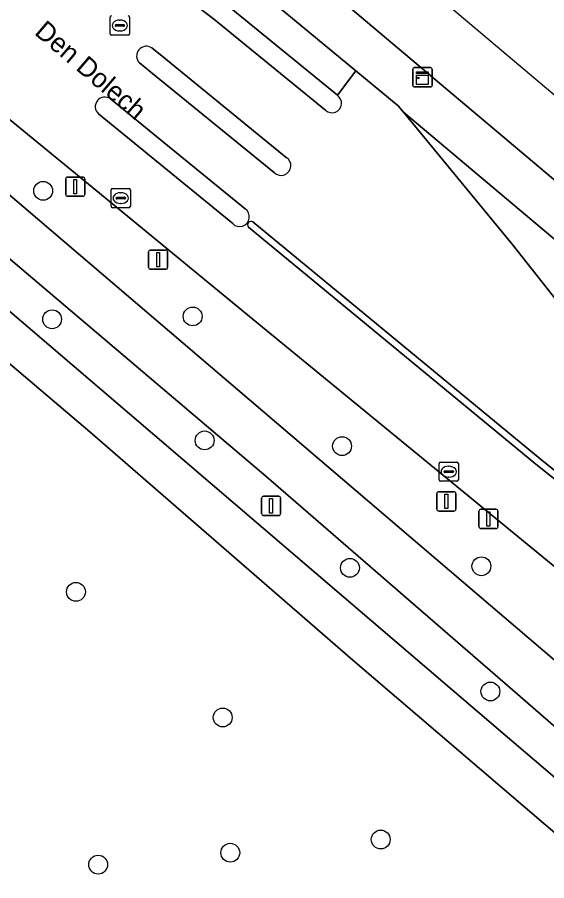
# Model space of a CAD drawing. Extents: x 161477 to 163040, y 383680 to 384871.
# Drawn here: x 161706.02 to 161733.53, y 384492.44 to 384537.26 of the extents above; entities that cross this region are included whole.
import ezdxf

# ---------------------------------------------------------------- set-up
doc = ezdxf.new("R2010")
doc.units = 0
for name, color, linetype in [('IMGEO_Berm_groen', 7, 'Continuous'), ('IMGEO_Boom', 7, 'Continuous'), ('IMGEO_Fietspad_gesloten', 7, 'Continuous'), ('IMGEO_Groenvoorziening', 7, 'Continuous'), ('IMGEO_Hek', 7, 'Continuous'), ('IMGEO_Kast', 7, 'Continuous'), ('IMGEO_Kolk', 7, 'Continuous'), ('IMGEO_Lichtmast', 7, 'Continuous'), ('IMGEO_Openbare_ruimte_label', 7, 'Continuous'), ('IMGEO_Rijbaan_lokaal_gesloten', 7, 'Continuous'), ('IMGEO_Rioolput', 7, 'Continuous'), ('IMGEO_Verkeersbordpaal', 7, 'Continuous'), ('IMGEO_Verkeerseiland_open', 7, 'Continuous'), ('IMGEO_Voetpad_open', 7, 'Continuous')]:
    doc.layers.add(name, color=color, linetype=linetype)

msp = doc.modelspace()

# ---------------------------------------------------------------- linework, layer by layer
at = {"layer": 'IMGEO_Berm_groen'}
for points in [[(161678.56, 384547.407), (161677.753, 384545.804), (161681.058, 384542.99), (161731.371, 384500), (161746.134, 384487.423), (161749.434, 384491.319), (161747.506, 384491.552)], [(161742.471, 384493.27), (161738.494, 384496.491), (161732.151, 384501.995), (161718.936, 384513.436), (161679.396, 384546.949)], [(161718.281, 384521.57), (161710.962, 384527.577), (161699.909, 384536.614), (161698.057, 384534.466), (161738.175, 384500.28), (161743.793, 384495.549), (161744.856, 384494.9), (161745.876, 384494.553)], [(161747.505, 384494.173), (161751.746, 384494.05), (161748.886, 384496.485), (161744.99, 384499.712), (161736.359, 384506.763), (161728.362, 384513.296), (161718.281, 384521.57)]]:
    msp.add_lwpolyline(points, dxfattribs=at)
msp.add_lwpolyline([(161726.09, 384532.33), (161731.734, 384525.482), (161735.698, 384520.457), (161737.128, 384518.817), (161738.213, 384517.796), (161738.289, 384517.727), (161738.506, 384517.532), (161739.38, 384516.745), (161750.717, 384507.564), (161752.219, 384506.212), (161757.111, 384501.401), (161757.185, 384501.335), (161758.111, 384502.394), (161757.471, 384504.592), (161756.765, 384506.541)], close=True, dxfattribs=at)
at = {"layer": 'IMGEO_Boom'}
for centre in [(161707.364, 384528.249), (161715.13, 384521.73), (161707.826, 384521.581), (161715.753, 384515.295), (161722.89, 384514.999), (161723.301, 384508.681), (161730.13, 384508.76), (161709.066, 384507.434), (161730.595, 384502.262), (161716.69, 384500.914), (161724.9, 384494.578), (161717.084, 384493.895), (161710.221, 384493.274)]:
    msp.add_circle(centre, 0.489, dxfattribs=at)
at = {"layer": 'IMGEO_Fietspad_gesloten'}
for points in [[(161679.396, 384546.949), (161718.936, 384513.436), (161732.151, 384501.995), (161738.494, 384496.491), (161742.471, 384493.27)], [(161716.468, 384538.263), (161722.646, 384533.207), (161723.613, 384534.474), (161717.624, 384539.425)], [(161745.876, 384494.553), (161744.856, 384494.9), (161743.793, 384495.549), (161738.175, 384500.28), (161698.057, 384534.466)]]:
    msp.add_lwpolyline(points, dxfattribs=at)
at = {"layer": 'IMGEO_Groenvoorziening'}
for points in [[(161725.311, 384630.208), (161692.773, 384563.441), (161758.806, 384507.866), (161760.886, 384500.893), (161760.961, 384500.987), (161761.131, 384500.854)], [(161655.123, 384380.786), (161705.198, 384439.501), (161703.363, 384440.983), (161707.91, 384446.382), (161709.855, 384444.859), (161729.976, 384468.339), (161744.705, 384485.735), (161723.453, 384503.883), (161709.781, 384515.739), (161680.014, 384540.993), (161676.741, 384543.785), (161660.175, 384511.161), (161637.594, 384466.689), (161619.35, 384430.848), (161600.945, 384394.608), (161593.687, 384380.342), (161587.084, 384366.964)]]:
    msp.add_lwpolyline(points, dxfattribs=at)
at = {"layer": 'IMGEO_Hek'}
msp.add_lwpolyline([(161694.364, 384566.706), (161703.664, 384558.776), (161724.439, 384541.249), (161745.033, 384523.877), (161742.926, 384521.23)], dxfattribs=at)
at = {"layer": 'IMGEO_Kast'}
for p, q in [((161726.569, 384533.718), (161726.569, 384534.559)), ((161726.569, 384534.559), (161726.569, 384533.718)), ((161726.644, 384534.643), (161727.485, 384534.643)), ((161727.485, 384534.643), (161726.644, 384534.643)), ((161727.569, 384534.568), (161727.569, 384533.727)), ((161727.569, 384533.727), (161727.569, 384534.568)), ((161727.494, 384533.643), (161726.653, 384533.643)), ((161726.653, 384533.643), (161727.494, 384533.643))]:
    msp.add_line(p, q, dxfattribs=at)
for points in [[(161726.764, 384534.433), (161727.364, 384534.433), (161727.364, 384534.348), (161726.764, 384534.348), (161726.764, 384534.433)], [(161726.764, 384534.258), (161727.364, 384534.258), (161727.364, 384533.769), (161726.764, 384533.769), (161726.764, 384534.258)]]:
    msp.add_lwpolyline(points, dxfattribs=at)
msp.add_circle((161726.848, 384534.107), 0.0377, dxfattribs=at)
for centre, start, end in [((161726.647, 384534.565), 92.4484, 184.2845), ((161726.647, 384534.565), 92.4484, 184.2845), ((161727.491, 384534.565), 2.4484, 94.2845), ((161727.491, 384534.565), 2.4484, 94.2845), ((161726.647, 384533.721), 182.4484, 274.2845), ((161726.647, 384533.721), 182.4484, 274.2845), ((161727.491, 384533.721), 272.4484, 4.2845), ((161727.491, 384533.721), 272.4484, 4.2845)]:
    msp.add_arc(centre, 0.0779, start, end, dxfattribs=at)
at = {"layer": 'IMGEO_Kolk'}
for p, q in [((161710.893, 384527.446), (161710.893, 384528.298)), ((161710.968, 384528.372), (161711.82, 384528.372)), ((161711.381, 384528.152), (161711.406, 384528.152)), ((161711.894, 384528.298), (161711.894, 384527.446)), ((161711.152, 384527.866), (161711.152, 384527.878)), ((161711.59, 384527.829), (161711.192, 384527.829)), ((161711.195, 384527.915), (161711.593, 384527.915)), ((161711.404, 384527.592), (161711.379, 384527.592)), ((161711.636, 384527.878), (161711.636, 384527.866)), ((161711.82, 384527.372), (161710.968, 384527.372)), ((161727.932, 384513.247), (161727.932, 384514.099)), ((161728.007, 384514.173), (161728.859, 384514.173)), ((161728.933, 384514.099), (161728.933, 384513.247)), ((161728.191, 384513.667), (161728.191, 384513.679)), ((161728.629, 384513.63), (161728.231, 384513.63)), ((161728.234, 384513.716), (161728.632, 384513.716)), ((161728.42, 384513.953), (161728.445, 384513.953)), ((161728.675, 384513.679), (161728.675, 384513.667)), ((161728.443, 384513.393), (161728.418, 384513.393)), ((161728.859, 384513.173), (161728.007, 384513.173))]:
    msp.add_line(p, q, dxfattribs=at)
for points in [[(161710.893, 384527.446), (161710.893, 384528.298)], [(161710.968, 384528.372), (161711.82, 384528.372)], [(161711.894, 384528.298), (161711.894, 384527.446)], [(161711.82, 384527.372), (161710.968, 384527.372)], [(161727.932, 384513.247), (161727.932, 384514.099)], [(161728.007, 384514.173), (161728.859, 384514.173)], [(161728.933, 384514.099), (161728.933, 384513.247)], [(161728.859, 384513.173), (161728.007, 384513.173)]]:
    msp.add_lwpolyline(points, dxfattribs=at)
for centre, radius, start, end in [((161710.97, 384528.296), 0.0765, 91.552, 178.448), ((161710.97, 384528.296), 0.0765, 91.552, 178.448), ((161711.818, 384528.296), 0.0765, 1.552, 88.448), ((161711.818, 384528.296), 0.0765, 1.552, 88.448), ((161711.192, 384527.875), 0.0403, 85.8775, 175.7526), ((161711.189, 384527.865), 0.0366, 178.938, 274.7102), ((161711.593, 384527.872), 0.043, 264.8664, 352.4533), ((161711.597, 384527.877), 0.0386, 1.7309, 96.639), ((161710.97, 384527.448), 0.0765, 181.552, 268.448), ((161710.97, 384527.448), 0.0765, 181.552, 268.448), ((161711.818, 384527.448), 0.0765, 271.552, 358.448), ((161711.818, 384527.448), 0.0765, 271.552, 358.448), ((161728.009, 384514.097), 0.0765, 91.552, 178.448), ((161728.009, 384514.097), 0.0765, 91.552, 178.448), ((161728.857, 384514.097), 0.0765, 1.552, 88.448), ((161728.857, 384514.097), 0.0765, 1.552, 88.448), ((161728.231, 384513.676), 0.0403, 85.8775, 175.7526), ((161728.228, 384513.666), 0.0366, 178.938, 274.7102), ((161728.632, 384513.673), 0.043, 264.8664, 352.4533), ((161728.636, 384513.678), 0.0386, 1.7309, 96.639), ((161728.009, 384513.249), 0.0765, 181.552, 268.448), ((161728.009, 384513.249), 0.0765, 181.552, 268.448), ((161728.857, 384513.249), 0.0765, 271.552, 358.448), ((161728.857, 384513.249), 0.0765, 271.552, 358.448)]:
    msp.add_arc(centre, radius, start, end, dxfattribs=at)
for centre, major_axis, ratio, start_param, end_param in [((161711.38, 384527.872), (-0.387, 0.002), 0.722429, 4.712389, 7.853982), ((161711.405, 384527.872), (-0.39, 0.002), 0.717154, 1.570796, 4.712389), ((161728.419, 384513.673), (-0.387, 0.002), 0.722429, 4.712389, 7.853982), ((161728.444, 384513.673), (-0.39, 0.002), 0.717154, 1.570796, 4.712389)]:
    msp.add_ellipse(centre, major_axis=major_axis, ratio=ratio, start_param=start_param, end_param=end_param, dxfattribs=at)
at = {"layer": 'IMGEO_Lichtmast'}
for p, q in [((161708.632, 384528.964), (161709.422, 384528.964)), ((161709.422, 384528.964), (161708.632, 384528.964)), ((161708.532, 384528.064), (161708.532, 384528.864)), ((161708.532, 384528.864), (161708.532, 384528.064)), ((161709.522, 384528.864), (161709.522, 384528.064)), ((161709.522, 384528.064), (161709.522, 384528.864)), ((161709.422, 384527.964), (161708.632, 384527.964)), ((161708.632, 384527.964), (161709.422, 384527.964)), ((161712.84, 384524.276), (161712.84, 384525.076)), ((161712.84, 384525.076), (161712.84, 384524.276)), ((161712.94, 384525.176), (161713.73, 384525.176)), ((161713.73, 384525.176), (161712.94, 384525.176)), ((161713.83, 384525.076), (161713.83, 384524.276)), ((161713.83, 384524.276), (161713.83, 384525.076)), ((161713.73, 384524.176), (161712.94, 384524.176)), ((161712.94, 384524.176), (161713.73, 384524.176)), ((161718.708, 384511.498), (161718.708, 384512.298)), ((161718.708, 384512.298), (161718.708, 384511.498)), ((161718.808, 384512.398), (161719.598, 384512.398)), ((161719.598, 384512.398), (161718.808, 384512.398)), ((161719.698, 384512.298), (161719.698, 384511.498)), ((161719.698, 384511.498), (161719.698, 384512.298)), ((161727.815, 384511.73), (161727.815, 384512.53)), ((161727.815, 384512.53), (161727.815, 384511.73)), ((161727.915, 384512.63), (161728.705, 384512.63)), ((161728.705, 384512.63), (161727.915, 384512.63)), ((161728.805, 384512.53), (161728.805, 384511.73)), ((161728.805, 384511.73), (161728.805, 384512.53)), ((161719.598, 384511.398), (161718.808, 384511.398)), ((161718.808, 384511.398), (161719.598, 384511.398)), ((161728.705, 384511.63), (161727.915, 384511.63)), ((161727.915, 384511.63), (161728.705, 384511.63))]:
    msp.add_line(p, q, dxfattribs=at)
for points in [[(161708.952, 384528.839), (161709.102, 384528.839), (161709.102, 384528.089), (161708.952, 384528.089), (161708.952, 384528.839)], [(161713.26, 384525.051), (161713.41, 384525.051), (161713.41, 384524.301), (161713.26, 384524.301), (161713.26, 384525.051)], [(161728.235, 384512.505), (161728.385, 384512.505), (161728.385, 384511.755), (161728.235, 384511.755), (161728.235, 384512.505)], [(161719.128, 384512.273), (161719.278, 384512.273), (161719.278, 384511.523), (161719.128, 384511.523), (161719.128, 384512.273)]]:
    msp.add_lwpolyline(points, dxfattribs=at)
for centre, start, end in [((161708.632, 384528.864), 90, 180), ((161708.632, 384528.864), 90, 180), ((161709.422, 384528.864), 0, 90), ((161709.422, 384528.864), 360, 90), ((161708.632, 384528.064), 180, 270), ((161708.632, 384528.064), 180, 270), ((161709.422, 384528.064), 270, 0), ((161709.422, 384528.064), 270, 0), ((161712.94, 384525.076), 90, 180), ((161712.94, 384525.076), 90, 180), ((161713.73, 384525.076), 0, 90), ((161713.73, 384525.076), 360, 90), ((161712.94, 384524.276), 180, 270), ((161712.94, 384524.276), 180, 270), ((161713.73, 384524.276), 270, 0), ((161713.73, 384524.276), 270, 0), ((161718.808, 384512.298), 90, 180), ((161718.808, 384512.298), 90, 180), ((161719.598, 384512.298), 0, 90), ((161719.598, 384512.298), 360, 90), ((161727.915, 384512.53), 90, 180), ((161727.915, 384512.53), 90, 180), ((161728.705, 384512.53), 0, 90), ((161728.705, 384512.53), 360, 90), ((161718.808, 384511.498), 180, 270), ((161718.808, 384511.498), 180, 270), ((161719.598, 384511.498), 270, 0), ((161719.598, 384511.498), 270, 0), ((161727.915, 384511.73), 180, 270), ((161727.915, 384511.73), 180, 270), ((161728.705, 384511.73), 270, 0), ((161728.705, 384511.73), 270, 0)]:
    msp.add_arc(centre, 0.1, start, end, dxfattribs=at)
at = {"layer": 'IMGEO_Rijbaan_lokaal_gesloten'}
for points in [[(161722.044, 384532.421), (161716.216, 384537.169), (161711.444, 384540.818)], [(161699.909, 384536.614), (161710.962, 384527.577), (161718.281, 384521.57), (161728.362, 384513.296), (161736.359, 384506.763)], [(161713.011, 384535.666), (161713.624, 384535.169), (161719.996, 384529.987)], [(161712.954, 384534.417), (161712.364, 384534.895)], [(161719.376, 384529.19), (161712.954, 384534.417)], [(161726.09, 384532.33), (161725.811, 384532.656), (161723.613, 384534.474), (161722.646, 384533.207)], [(161710.855, 384533.023), (161711.435, 384532.549), (161711.532, 384532.47), (161713.639, 384530.75)], [(161717.208, 384526.545), (161710.231, 384532.253)], [(161735.698, 384520.457), (161731.734, 384525.482), (161726.09, 384532.33)], [(161713.639, 384530.75), (161717.85, 384527.315)], [(161718.26, 384526.644), (161733.182, 384514.341), (161736.308, 384511.837), (161739.469, 384509.368), (161756.636, 384495.993)], [(161756.636, 384495.993), (161756.418, 384495.733), (161739.259, 384509.1), (161736.098, 384511.571), (161732.954, 384514.063), (161718.034, 384526.362)]]:
    msp.add_lwpolyline(points, dxfattribs=at)
for centre, radius, start, end in [((161712.723, 384535.251), 0.505, 55.2503, 224.7449), ((161710.565, 384532.62), 0.496, 54.2569, 227.7012), ((161722.366, 384532.798), 0.496, 229.4221, 55.6807), ((161719.726, 384529.557), 0.507, 226.3478, 57.8922), ((161717.57, 384526.896), 0.504, 224.091, 56.2686), ((161718.17, 384526.485), 0.183, 60.4706, 222.1107)]:
    msp.add_arc(centre, radius, start, end, dxfattribs=at)
at = {"layer": 'IMGEO_Rioolput'}
for p, q in [((161710.846, 384536.406), (161710.846, 384537.258)), ((161711.334, 384537.112), (161711.359, 384537.112)), ((161711.847, 384537.258), (161711.847, 384536.406)), ((161711.105, 384536.826), (161711.105, 384536.838)), ((161711.543, 384536.789), (161711.145, 384536.789)), ((161711.148, 384536.875), (161711.546, 384536.875)), ((161711.357, 384536.552), (161711.332, 384536.552)), ((161711.589, 384536.838), (161711.589, 384536.826)), ((161711.773, 384536.332), (161710.921, 384536.332))]:
    msp.add_line(p, q, dxfattribs=at)
for points in [[(161710.846, 384536.406), (161710.846, 384537.258)], [(161711.847, 384537.258), (161711.847, 384536.406)], [(161711.773, 384536.332), (161710.921, 384536.332)]]:
    msp.add_lwpolyline(points, dxfattribs=at)
for centre, radius, start, end in [((161710.923, 384537.256), 0.0765, 91.552, 178.448), ((161710.923, 384537.256), 0.0765, 91.552, 178.448), ((161711.771, 384537.256), 0.0765, 1.552, 88.448), ((161711.771, 384537.256), 0.0765, 1.552, 88.448), ((161711.145, 384536.835), 0.0403, 85.8775, 175.7526), ((161711.142, 384536.825), 0.0366, 178.938, 274.7102), ((161711.546, 384536.832), 0.043, 264.8664, 352.4533), ((161711.55, 384536.837), 0.0386, 1.7309, 96.639), ((161710.923, 384536.408), 0.0765, 181.552, 268.448), ((161710.923, 384536.408), 0.0765, 181.552, 268.448), ((161711.771, 384536.408), 0.0765, 271.552, 358.448), ((161711.771, 384536.408), 0.0765, 271.552, 358.448)]:
    msp.add_arc(centre, radius, start, end, dxfattribs=at)
for centre, major_axis, ratio, start_param, end_param in [((161711.333, 384536.832), (-0.387, 0.002), 0.722429, 4.712389, 7.853982), ((161711.358, 384536.832), (-0.39, 0.002), 0.717154, 1.570796, 4.712389)]:
    msp.add_ellipse(centre, major_axis=major_axis, ratio=ratio, start_param=start_param, end_param=end_param, dxfattribs=at)
at = {"layer": 'IMGEO_Verkeersbordpaal'}
for p, q in [((161729.998, 384510.821), (161729.998, 384511.621)), ((161729.998, 384511.621), (161729.998, 384510.821)), ((161730.098, 384511.721), (161730.888, 384511.721)), ((161730.888, 384511.721), (161730.098, 384511.721)), ((161730.988, 384511.621), (161730.988, 384510.821)), ((161730.988, 384510.821), (161730.988, 384511.621)), ((161730.888, 384510.721), (161730.098, 384510.721)), ((161730.098, 384510.721), (161730.888, 384510.721))]:
    msp.add_line(p, q, dxfattribs=at)
msp.add_lwpolyline([(161730.418, 384511.596), (161730.568, 384511.596), (161730.568, 384510.846), (161730.418, 384510.846), (161730.418, 384511.596)], dxfattribs=at)
for centre, start, end in [((161730.098, 384511.621), 90, 180), ((161730.098, 384511.621), 90, 180), ((161730.888, 384511.621), 0, 90), ((161730.888, 384511.621), 360, 90), ((161730.098, 384510.821), 180, 270), ((161730.098, 384510.821), 180, 270), ((161730.888, 384510.821), 270, 0), ((161730.888, 384510.821), 270, 0)]:
    msp.add_arc(centre, 0.1, start, end, dxfattribs=at)
at = {"layer": 'IMGEO_Verkeerseiland_open'}
for points in [[(161703.129, 384547.68), (161699.289, 384550.909), (161698.747, 384550.205), (161704.786, 384545.311), (161711.444, 384540.818), (161716.216, 384537.169), (161722.044, 384532.421)], [(161722.646, 384533.207), (161716.468, 384538.263)], [(161713.624, 384535.169), (161713.011, 384535.666)], [(161719.996, 384529.987), (161713.624, 384535.169)], [(161712.364, 384534.895), (161712.954, 384534.417), (161719.376, 384529.19)], [(161713.639, 384530.75), (161711.532, 384532.47), (161711.435, 384532.549), (161710.855, 384533.023)], [(161710.231, 384532.253), (161717.208, 384526.545)], [(161717.85, 384527.315), (161713.639, 384530.75)], [(161718.034, 384526.362), (161732.954, 384514.063), (161736.098, 384511.571), (161739.259, 384509.1), (161756.418, 384495.733), (161756.636, 384495.993), (161739.469, 384509.368), (161736.308, 384511.837), (161733.182, 384514.341), (161718.26, 384526.644)]]:
    msp.add_lwpolyline(points, dxfattribs=at)
for centre, radius, start, end in [((161712.723, 384535.251), 0.505, 55.2503, 224.7449), ((161710.565, 384532.62), 0.496, 54.2569, 227.7012), ((161722.366, 384532.798), 0.496, 229.4221, 55.6807), ((161719.726, 384529.557), 0.507, 226.3478, 57.8922), ((161717.57, 384526.896), 0.504, 224.091, 56.2686), ((161718.17, 384526.485), 0.183, 60.4706, 222.1107)]:
    msp.add_arc(centre, radius, start, end, dxfattribs=at)
at = {"layer": 'IMGEO_Voetpad_open'}
msp.add_lwpolyline([(161717.624, 384539.425), (161723.613, 384534.474), (161725.811, 384532.656), (161726.09, 384532.33), (161756.765, 384506.541), (161757.471, 384504.592), (161758.111, 384502.394), (161757.185, 384501.335), (161758.742, 384499.932), (161758.86, 384499.826), (161759.408, 384499.333), (161759.518, 384499.242), (161759.565, 384499.296), (161760.886, 384500.893), (161758.806, 384507.866), (161692.773, 384563.441)], dxfattribs=at)
msp.add_lwpolyline([(161681.058, 384542.99), (161677.753, 384545.804), (161676.741, 384543.785), (161680.014, 384540.993), (161709.781, 384515.739), (161723.453, 384503.883), (161744.705, 384485.735), (161744.854, 384485.911), (161746.134, 384487.423), (161731.371, 384500)], close=True, dxfattribs=at)

# ---------------------------------------------------------------- texts
at = {"layer": 'IMGEO_Openbare_ruimte_label'}
msp.add_text('Den Dolech', height=1, rotation=319.5044, dxfattribs=at).set_placement((161706.861, 384536.407))

doc.saveas('drawing.dxf')
